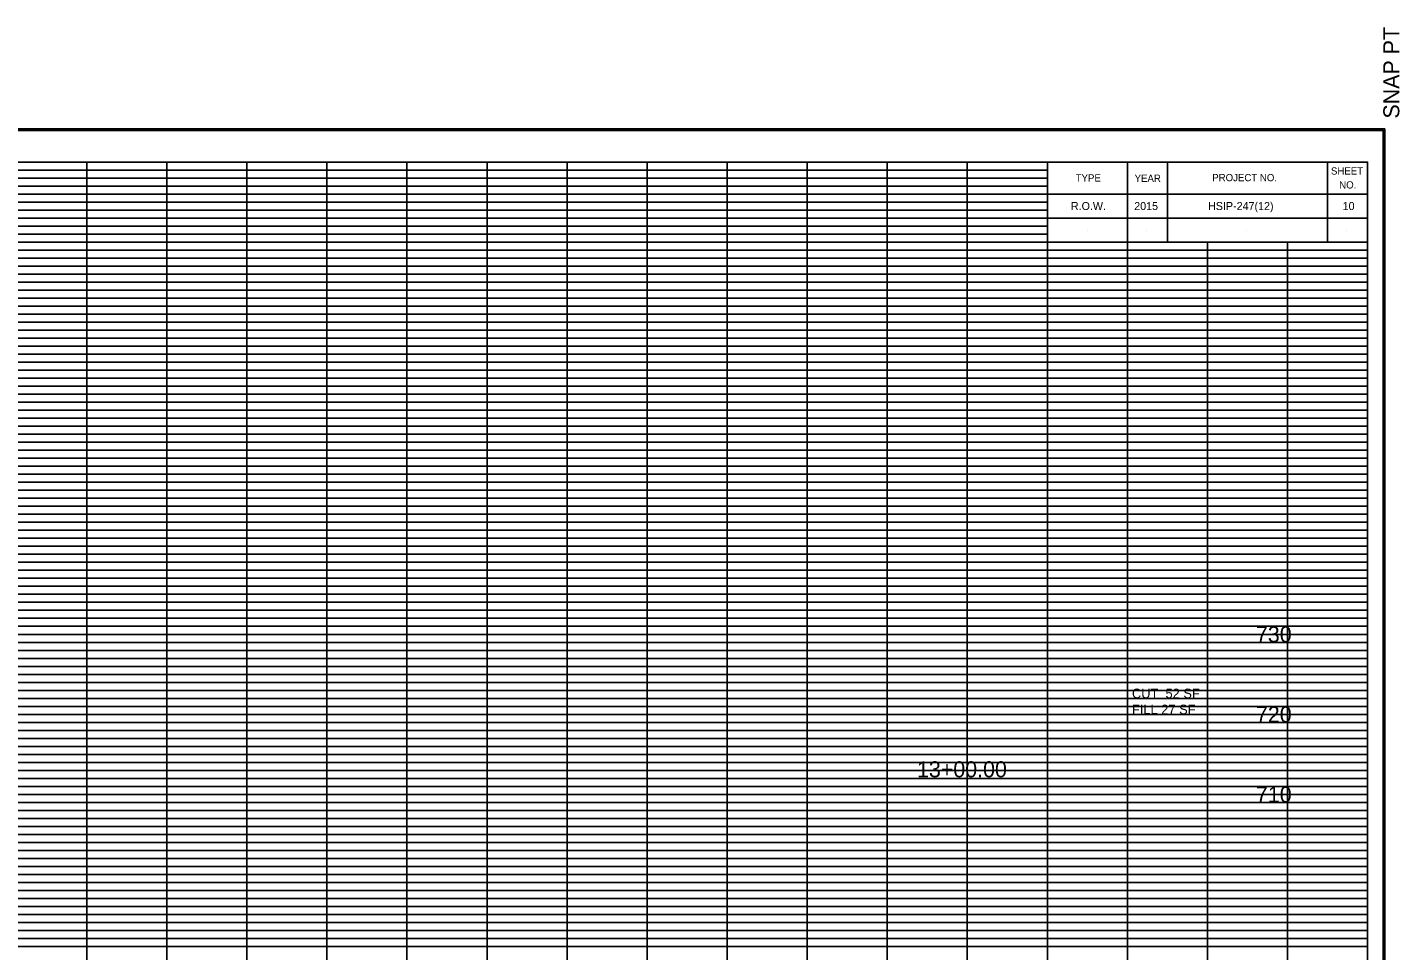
# Model space of a CAD drawing. Extents: x -200 to 1704, y -325 to 2307.
# Drawn here: x 1152.6 to 1324, y 1111.5 to 1226.8 of the extents above; entities that cross this region are included whole.
import ezdxf

# ---------------------------------------------------------------- set-up
doc = ezdxf.new("R2010")
doc.units = 0
for name, color, linetype in [('DESIGN - SCRATCH - User 1', 7, 'Continuous'), ('DESIGN - SHEET - Corner Text', 7, 'Continuous'), ('DESIGN - SHEET - Light Grid', 7, 'Continuous'), ('DESIGN - SHEET - Linework', 7, 'Continuous'), ('DESIGN - SHEET - Plot Shape', 7, 'Continuous'), ('DESIGN - TYPICAL - Text', 7, 'Continuous')]:
    doc.layers.add(name, color=color, linetype=linetype)

msp = doc.modelspace()

# ---------------------------------------------------------------- linework, layer by layer
at = {"layer": 'DESIGN - SCRATCH - User 1'}
for p, q in [((1285, 1204.5), (1285, 1204.5)), ((1292.4, 1204.5), (1292.4, 1204.5)), ((1304.9, 1204.5), (1304.9, 1204.5)), ((1317.4, 1204.5), (1317.4, 1204.5)), ((1285, 1201.5), (1285, 1201.5)), ((1292.4, 1201.5), (1292.4, 1201.5)), ((1304.9, 1201.5), (1304.9, 1201.5)), ((1317.4, 1201.5), (1317.4, 1201.5))]:
    msp.add_line(p, q, dxfattribs=at)
at = {"layer": 'DESIGN - SHEET - Light Grid'}
for p, q in [((1080, 1209), (1160, 1209)), ((1160, 1209), (1240, 1209)), ((1240, 1209), (1280, 1209)), ((1080, 1208), (1160, 1208)), ((1080, 1207), (1160, 1207)), ((1160, 1208), (1240, 1208)), ((1160, 1207), (1240, 1207)), ((1240, 1208), (1280, 1208)), ((1240, 1207), (1280, 1207)), ((1080, 1206), (1160, 1206)), ((1160, 1206), (1240, 1206)), ((1240, 1206), (1280, 1206)), ((1080, 1205), (1160, 1205)), ((1080, 1204), (1160, 1204)), ((1160, 1205), (1240, 1205)), ((1160, 1204), (1240, 1204)), ((1240, 1205), (1280, 1205)), ((1240, 1204), (1280, 1204)), ((1080, 1203), (1160, 1203)), ((1080, 1202), (1160, 1202)), ((1160, 1203), (1240, 1203)), ((1160, 1202), (1240, 1202)), ((1240, 1203), (1280, 1203)), ((1240, 1202), (1280, 1202)), ((1080, 1201), (1160, 1201)), ((1160, 1201), (1240, 1201)), ((1240, 1201), (1280, 1201)), ((1080, 1199), (1160, 1199)), ((1160, 1199), (1240, 1199)), ((1240, 1199), (1320, 1199)), ((1080, 1198), (1160, 1198)), ((1080, 1197), (1160, 1197)), ((1160, 1198), (1240, 1198)), ((1160, 1197), (1240, 1197)), ((1240, 1198), (1320, 1198)), ((1240, 1197), (1320, 1197)), ((1080, 1196), (1160, 1196)), ((1080, 1195), (1160, 1195)), ((1160, 1196), (1240, 1196)), ((1160, 1195), (1240, 1195)), ((1240, 1196), (1320, 1196)), ((1240, 1195), (1320, 1195)), ((1080, 1194), (1160, 1194)), ((1160, 1194), (1240, 1194)), ((1240, 1194), (1320, 1194)), ((1080, 1193), (1160, 1193)), ((1080, 1192), (1160, 1192)), ((1160, 1193), (1240, 1193)), ((1160, 1192), (1240, 1192)), ((1240, 1193), (1320, 1193)), ((1240, 1192), (1320, 1192)), ((1080, 1191), (1160, 1191)), ((1160, 1191), (1240, 1191)), ((1240, 1191), (1320, 1191)), ((1080, 1189), (1160, 1189)), ((1080, 1188), (1160, 1188)), ((1160, 1189), (1240, 1189)), ((1160, 1188), (1240, 1188)), ((1240, 1189), (1320, 1189)), ((1240, 1188), (1320, 1188)), ((1080, 1187), (1160, 1187)), ((1160, 1187), (1240, 1187)), ((1240, 1187), (1320, 1187)), ((1080, 1186), (1160, 1186)), ((1080, 1185), (1160, 1185)), ((1160, 1186), (1240, 1186)), ((1160, 1185), (1240, 1185)), ((1240, 1186), (1320, 1186)), ((1240, 1185), (1320, 1185)), ((1080, 1184), (1160, 1184)), ((1080, 1183), (1160, 1183)), ((1160, 1184), (1240, 1184)), ((1160, 1183), (1240, 1183)), ((1240, 1184), (1320, 1184)), ((1240, 1183), (1320, 1183)), ((1080, 1182), (1160, 1182)), ((1160, 1182), (1240, 1182)), ((1240, 1182), (1320, 1182)), ((1080, 1181), (1160, 1181)), ((1160, 1181), (1240, 1181)), ((1240, 1181), (1320, 1181)), ((1080, 1179), (1160, 1179)), ((1080, 1178), (1160, 1178)), ((1160, 1179), (1240, 1179)), ((1160, 1178), (1240, 1178)), ((1240, 1179), (1320, 1179)), ((1240, 1178), (1320, 1178)), ((1080, 1177), (1160, 1177)), ((1080, 1176), (1160, 1176)), ((1160, 1177), (1240, 1177)), ((1160, 1176), (1240, 1176)), ((1240, 1177), (1320, 1177)), ((1240, 1176), (1320, 1176)), ((1080, 1175), (1160, 1175)), ((1160, 1175), (1240, 1175)), ((1240, 1175), (1320, 1175)), ((1080, 1174), (1160, 1174)), ((1080, 1173), (1160, 1173)), ((1160, 1174), (1240, 1174)), ((1160, 1173), (1240, 1173)), ((1240, 1174), (1320, 1174)), ((1240, 1173), (1320, 1173)), ((1080, 1172), (1160, 1172)), ((1080, 1171), (1160, 1171)), ((1160, 1172), (1240, 1172)), ((1160, 1171), (1240, 1171)), ((1240, 1172), (1320, 1172)), ((1240, 1171), (1320, 1171)), ((1080, 1169), (1160, 1169)), ((1080, 1168), (1160, 1168)), ((1160, 1169), (1240, 1169)), ((1160, 1168), (1240, 1168)), ((1240, 1169), (1320, 1169)), ((1240, 1168), (1320, 1168)), ((1080, 1167), (1160, 1167)), ((1080, 1166), (1160, 1166)), ((1160, 1167), (1240, 1167)), ((1160, 1166), (1240, 1166)), ((1240, 1167), (1320, 1167)), ((1240, 1166), (1320, 1166)), ((1080, 1165), (1160, 1165)), ((1080, 1164), (1160, 1164)), ((1160, 1165), (1240, 1165)), ((1160, 1164), (1240, 1164)), ((1240, 1165), (1320, 1165)), ((1240, 1164), (1320, 1164)), ((1080, 1163), (1160, 1163)), ((1160, 1163), (1240, 1163)), ((1240, 1163), (1320, 1163)), ((1080, 1162), (1160, 1162)), ((1080, 1161), (1160, 1161)), ((1160, 1162), (1240, 1162)), ((1160, 1161), (1240, 1161)), ((1240, 1162), (1320, 1162)), ((1240, 1161), (1320, 1161)), ((1080, 1159), (1160, 1159)), ((1160, 1159), (1240, 1159)), ((1240, 1159), (1320, 1159)), ((1080, 1158), (1160, 1158)), ((1160, 1158), (1240, 1158)), ((1240, 1158), (1320, 1158)), ((1080, 1157), (1160, 1157)), ((1080, 1156), (1160, 1156)), ((1160, 1157), (1240, 1157)), ((1160, 1156), (1240, 1156)), ((1240, 1157), (1320, 1157)), ((1240, 1156), (1320, 1156)), ((1080, 1155), (1160, 1155)), ((1080, 1154), (1160, 1154)), ((1160, 1155), (1240, 1155)), ((1160, 1154), (1240, 1154)), ((1240, 1155), (1320, 1155)), ((1240, 1154), (1320, 1154)), ((1080, 1153), (1160, 1153)), ((1080, 1152), (1160, 1152)), ((1160, 1153), (1240, 1153)), ((1160, 1152), (1240, 1152)), ((1240, 1153), (1320, 1153)), ((1240, 1152), (1320, 1152)), ((1080, 1151), (1160, 1151)), ((1160, 1151), (1240, 1151)), ((1240, 1151), (1320, 1151)), ((1080, 1149), (1160, 1149)), ((1160, 1149), (1240, 1149)), ((1240, 1149), (1320, 1149)), ((1080, 1148), (1160, 1148)), ((1080, 1147), (1160, 1147)), ((1160, 1148), (1240, 1148)), ((1160, 1147), (1240, 1147)), ((1240, 1148), (1320, 1148)), ((1240, 1147), (1320, 1147)), ((1080, 1146), (1160, 1146)), ((1160, 1146), (1240, 1146)), ((1240, 1146), (1320, 1146)), ((1080, 1145), (1160, 1145)), ((1080, 1144), (1160, 1144)), ((1160, 1145), (1240, 1145)), ((1160, 1144), (1240, 1144)), ((1240, 1145), (1320, 1145)), ((1240, 1144), (1320, 1144)), ((1080, 1143), (1160, 1143)), ((1080, 1142), (1160, 1142)), ((1160, 1143), (1240, 1143)), ((1160, 1142), (1240, 1142)), ((1240, 1143), (1320, 1143)), ((1240, 1142), (1320, 1142)), ((1080, 1141), (1160, 1141)), ((1160, 1141), (1240, 1141)), ((1240, 1141), (1320, 1141)), ((1080, 1139), (1160, 1139)), ((1160, 1139), (1240, 1139)), ((1240, 1139), (1320, 1139)), ((1080, 1138), (1160, 1138)), ((1080, 1137), (1160, 1137)), ((1160, 1138), (1240, 1138)), ((1160, 1137), (1240, 1137)), ((1240, 1138), (1320, 1138)), ((1240, 1137), (1320, 1137)), ((1080, 1136), (1160, 1136)), ((1080, 1135), (1160, 1135)), ((1160, 1136), (1240, 1136)), ((1160, 1135), (1240, 1135)), ((1240, 1136), (1320, 1136)), ((1240, 1135), (1320, 1135)), ((1080, 1134), (1160, 1134)), ((1160, 1134), (1240, 1134)), ((1240, 1134), (1320, 1134)), ((1080, 1133), (1160, 1133)), ((1080, 1132), (1160, 1132)), ((1160, 1133), (1240, 1133)), ((1160, 1132), (1240, 1132)), ((1240, 1133), (1320, 1133)), ((1240, 1132), (1320, 1132)), ((1080, 1131), (1160, 1131)), ((1160, 1131), (1240, 1131)), ((1240, 1131), (1320, 1131)), ((1080, 1129), (1160, 1129)), ((1080, 1128), (1160, 1128)), ((1160, 1129), (1240, 1129)), ((1160, 1128), (1240, 1128)), ((1240, 1129), (1320, 1129)), ((1240, 1128), (1320, 1128)), ((1080, 1127), (1160, 1127)), ((1160, 1127), (1240, 1127)), ((1240, 1127), (1320, 1127)), ((1080, 1126), (1160, 1126)), ((1080, 1125), (1160, 1125)), ((1160, 1126), (1240, 1126)), ((1160, 1125), (1240, 1125)), ((1240, 1126), (1320, 1126)), ((1240, 1125), (1320, 1125)), ((1080, 1124), (1160, 1124)), ((1080, 1123), (1160, 1123)), ((1160, 1124), (1240, 1124)), ((1160, 1123), (1240, 1123)), ((1240, 1124), (1320, 1124)), ((1240, 1123), (1320, 1123)), ((1080, 1122), (1160, 1122)), ((1160, 1122), (1240, 1122)), ((1240, 1122), (1320, 1122)), ((1080, 1121), (1160, 1121)), ((1160, 1121), (1240, 1121)), ((1240, 1121), (1320, 1121)), ((1080, 1119), (1160, 1119)), ((1080, 1118), (1160, 1118)), ((1160, 1119), (1240, 1119)), ((1160, 1118), (1240, 1118)), ((1240, 1119), (1320, 1119)), ((1240, 1118), (1320, 1118)), ((1080, 1117), (1160, 1117)), ((1080, 1116), (1160, 1116)), ((1160, 1117), (1240, 1117)), ((1160, 1116), (1240, 1116)), ((1240, 1117), (1320, 1117)), ((1240, 1116), (1320, 1116)), ((1080, 1115), (1160, 1115)), ((1160, 1115), (1240, 1115)), ((1240, 1115), (1320, 1115)), ((1080, 1114), (1160, 1114)), ((1080, 1113), (1160, 1113)), ((1160, 1114), (1240, 1114)), ((1160, 1113), (1240, 1113)), ((1240, 1114), (1320, 1114)), ((1240, 1113), (1320, 1113)), ((1080, 1112), (1160, 1112)), ((1160, 1112), (1240, 1112)), ((1240, 1112), (1320, 1112))]:
    msp.add_line(p, q, dxfattribs=at)
at = {"layer": 'DESIGN - SHEET - Linework'}
for p, q in [((981.77, 1214.14), (1322.17, 1214.14)), ((1322.17, 1214.14), (1322.17, 995.86)), ((1160, 1000), (1160, 1210)), ((1170, 1000), (1170, 1210)), ((1180, 1000), (1180, 1210)), ((1190, 1000), (1190, 1210)), ((1200, 1000), (1200, 1210)), ((1210, 1000), (1210, 1210)), ((1220, 1000), (1220, 1210)), ((1230, 1000), (1230, 1210)), ((1240, 1000), (1240, 1210)), ((1250, 1000), (1250, 1210)), ((1260, 1000), (1260, 1210)), ((1270, 1000), (1270, 1210)), ((1000, 1200), (1280, 1200)), ((1280, 1000), (1280, 1200)), ((1290, 1000), (1290, 1200)), ((1300, 1000), (1300, 1200)), ((1310, 1000), (1310, 1200)), ((1000, 1190), (1320, 1190)), ((1000, 1180), (1320, 1180)), ((1000, 1170), (1320, 1170)), ((1000, 1160), (1320, 1160)), ((1000, 1150), (1320, 1150)), ((1000, 1140), (1320, 1140)), ((1000, 1130), (1320, 1130)), ((1000, 1120), (1320, 1120))]:
    msp.add_line(p, q, dxfattribs=at)
for points in [[(1000, 1210), (1000, 1000), (1320, 1000), (1320, 1210), (1000, 1210)], [(1280, 1210), (1280, 1200), (1320, 1200), (1320, 1210), (1315, 1210), (1315, 1200), (1295, 1200), (1295, 1210), (1290, 1210), (1290, 1200), (1320, 1200), (1280, 1200), (1280, 1203), (1320, 1203), (1320, 1206), (1280, 1206)]]:
    msp.add_lwpolyline(points, dxfattribs=at)
at = {"layer": 'DESIGN - SHEET - Plot Shape'}
for points in [[(981.97, 1213.94), (1321.97, 1213.94), (1321.97, 996.06), (981.97, 996.06)], [(991.5, 1210), (1320, 1210), (1320, 997.5), (991.5, 997.5)]]:
    msp.add_lwpolyline(points, close=True, dxfattribs=at)

# ---------------------------------------------------------------- texts
at = {"layer": 'DESIGN - SHEET - Corner Text'}
msp.add_text('  SNAP PT', height=2, rotation=90, dxfattribs=at).set_placement((1323.97, 1213.94))
for s, height, p in [('TYPE', 0.9, (1283.54, 1207.56)), ('PROJECT NO.', 0.9, (1300.6, 1207.6)), ('SHEET', 0.9, (1315.43, 1208.43)), ('YEAR', 0.9, (1290.9, 1207.52)), ('NO.', 0.9, (1316.46, 1206.69)), ('R.O.W.', 1, (1282.94, 1204)), ('2015', 1, (1290.85, 1204)), ('HSIP-247(12)', 1, (1300.08, 1204)), ('10', 1, (1316.89, 1204))]:
    msp.add_text(s, height=height, dxfattribs=at).set_placement(p)
at = {"layer": 'DESIGN - TYPICAL - Text'}
for s, height, p in [('     730     ', 2, (1302.34, 1150)), ('CUT  52 SF', 1.2, (1290.57, 1143.02)), ('FILL 27 SF', 1.2, (1290.57, 1141.02)), ('     720     ', 2, (1302.34, 1140)), ('     13+00.00     ', 2, (1260, 1133.14)), ('     710     ', 2, (1302.34, 1130))]:
    msp.add_text(s, height=height, dxfattribs=at).set_placement(p)

doc.saveas('drawing.dxf')
